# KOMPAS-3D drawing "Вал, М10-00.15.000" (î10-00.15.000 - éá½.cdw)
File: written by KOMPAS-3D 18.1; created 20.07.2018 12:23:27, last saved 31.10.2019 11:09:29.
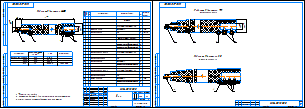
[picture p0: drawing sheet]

Sheets 1-2: A3, landscape

Document properties: Полное имя файла: D:\Magna\Магна Ins\Магна ins 10\М10-00.00.000\3Д\М10-00.15.000 - Вал.cdw; Масса: 0.519317; Форматы листов документа: 2xA3

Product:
- Part/product: Вал  | designation М10-00.15.000  | pos. 0
    Масса: 0.519317
    Раздел спецификации: Сборочные единицы
    Форматы листов документа: 2xA3
    Примечание: @100~)2xA3
    source file: М10-00.15.000 - Вал.cdw
  - Body: Тело 2
      Материал: Полипропилен  ГОСТ 26996-86 (density 900 kg/m3)
  - Body: Тело 1
      Материал: Полипропилен  ГОСТ 26996-86 (density 900 kg/m3)
  - Component [standard]: Винт A.М10-6gx40.21.12Х18Н10Т ГОСТ 11074-93  | pos. 4  | Материал: Сталь 12Х18Н10Т ГОСТ 5632-72; Масса: 0.0191; Раздел спецификации: Стандартные изделия; additional columns: А.М10-6gx40.21.12Х18Н10Т; Сталь 12Х18Н10Т ГОСТ 5632-72; source file: C:\Users\User\AppData\Local\Temp\..\..\..\..\..\Program Files\ASCON\KOMPAS-3D v18\Libs\PartLib\DATA\VAULT\methods\kompas\3d\PLib_Screw_GOST_11074-84_900.m3d
  - Component [detail]: Отбойник  | designation М1-00.25.004  | pos. 1  | Раздел спецификации: Детали; Форматы листов документа: A4; Примечание: Заим.; source file: \\192.168.87.28\Konstructor_doc\Магна\Магна Ins\Магна ins 1\Магна Ins 1-205-24В\М1-00.25.004 - Отбойник.cdw, \\192.168.87.28\Konstructor_doc\Магна\Магна Ins\Магна ins 1\Магна Ins 1-205-24В\М1-00.25.004 - Отбойник.m3d
  - Component [standard]: Винт A.М5-6gx12.21.12Х18Н10Т ГОСТ 8878-93  | qty 2  | pos. 3  | Материал: Сталь 12Х18Н10Т ГОСТ 5632-72; Масса: 0.0012; Раздел спецификации: Стандартные изделия; additional columns: А.М5-6gx12.21.12Х18Н10Т; Сталь 12Х18Н10Т ГОСТ 5632-72; source file: C:\Users\User\AppData\Local\Temp\..\..\..\..\..\Program Files\ASCON\KOMPAS-3D v18\Libs\PartLib\DATA\VAULT\methods\kompas\3d\PLib_Screw_GOST_8878-84_900.m3d
  - Component [detail]: Фиксатор  | designation М5-00.20.002  | pos. 1
      Материал: Труба 30х4-12Х18Н10Т ГОСТ 9940-81
      Масса: 0.1021
      Раздел спецификации: Детали
      Примечание: Заим.
      Плотность: 7900
      source file: ..\..\..\Магна ins 5\М5-00.00.000 - Насос Магна ins 5-C-N\3Д модель\М5-00.20.002 - Фиксатор.m3d
  - Component [detail]: Вал  | designation М10-00.15.001  | pos. 2
      Масса: 0.3957
      Раздел спецификации: Детали
      Форматы листов документа: 2xA3
      Примечание: @100~)2xA3
      Плотность: 2000
      source file: М10-00.15.001 - Вал.cdw, М10-00.15.001 - Вал.m3d
  - Component: Вал  | designation М10-00.15.001-01  | pos. 5  | Раздел спецификации: Стандартные изделия
  - Component: Винт A.М6-6gx16.21.12Х18Н10Т ГОСТ 8878-93  | pos. 7  | Раздел спецификации: Стандартные изделия
  - Component: Фиксатор  | designation М10-00.15.002  | pos. 6  | Раздел спецификации: Стандартные изделия; Форматы листов документа: А4; source file: М10-00.15.002 - Фиксатор.cdw
  - Component: Вал  | designation М10-00.15.001-02  | pos. 8  | Раздел спецификации: Стандартные изделия
  - Component: Фиксатор  | designation М11-00.01.002  | pos. 9  | Раздел спецификации: Стандартные изделия; Форматы листов документа: А4; Примечание: Заим.
  - Component: Винт A.М6-6gx16.21.12Х18Н10Т ГОСТ 8878-93  | pos. 10  | Раздел спецификации: Стандартные изделия

Title block, sheet 1: Наименование: Вал; designation: М10-00.15.000; Масса: 0,52; scale: 1:1; sheet number: 1; Количество листов документа: 2; organisation: АО «Астерион»; Форматы листов документа: A3; stored path: Z:\Магна\Магна Ins\Магна ins 10\М10-00.00.000\3Д\М10-00.15.000 - Вал.cdw; Разработал: Милов; Т. контр.: Лучихин; Утвердил: Милов
Title block, sheet 2: sheet number: 2

Views: Вид 1, Местный разрез 1, Местный разрез 2, Сверху, Проекционный вид 2, Вид 3, Вид 4
Referenced files in Z:\Магна\Магна Ins\Магна ins 10\М10-00.00.000\3Д\: М10-00.15.001 - Вал.m3d, М10-00.15.000 - Вал.a3d
Referenced files in Z:\Магна\Магна Ins\Магна ins 5\М5-00.00.000 - Насос Магна ins 5-C-N\3Д модель\: М5-00.20.002 - Фиксатор.m3d
Referenced files in D:\Magna\Магна Ins\Магна ins 10\М10-00.00.000\3Д\..\..\..\Магна ins 5\М5-00.00.000 - Насос Магна ins 5-C-N\3Д модель\: М5-00.20.002 - Фиксатор.m3d
Referenced files in D:\Magna\Магна Ins\Магна ins 10\М10-00.00.000\3Д\: М10-00.15.001 - Вал.m3d, М10-00.15.001 - Вал.cdw, М10-00.15.002 - Фиксатор.cdw, М10-00.15.000 - Вал.a3d
Referenced files in D:\Magna\Магна Ins\Магна ins 5\М5-00.00.000 - Насос Магна ins 5-C-N\3Д модель\: М5-00.20.002 - Фиксатор.m3d
Referenced files in C:\Program Files\ASCON\KOMPAS-3D v18\Libs\PartLib\DATA\VAULT\methods\kompas\3d\: PLib_Screw_GOST_8878-84_900.m3d, PLib_Screw_GOST_11074-84_900.m3d
Referenced files in C:\Program Files\ASCON\KOMPAS-3D V16\Libs\PartLib\DATA\vault\Methods\Kompas\3D\: PLib_Screw_GOST_8878-84_900.m3d
Referenced files in C:\Program Files\ASCON\KOMPAS-3D V16\Libs\PartLib\DATA\VAULT\Methods\kompas\3d\: PLib_Screw_GOST_11074-84_900.m3d
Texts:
  Габарит двигателя 63
  Длина погружной части
  L1, мм*
  L, мм
  L1 475 мм
  Габарит двигателя 71
  Габарит двигателя 80
  2D_Doc-graphic.lyt,1.000000-0-298842308658
  2D_Doc-graphic.lyt,1.000000-0-298491746024
  2D_Doc-graphic.lyt,1.000000-0-297339638027
  2D_Doc-graphic.lyt,1.000000-0-281262858143
  2D_Doc-graphic.lyt,1.000000-0-280836307480
  Фиксатор
  Заим.
  Труба 30х4-12Х18Н10Т ГОСТ 9940-81
  Винт A.М5-6gx12.21.12Х18Н10Т ГОСТ 8878-93
  Винт
  ГОСТ
  Сталь 12Х18Н10Т ГОСТ 5632-72
  @100~)2xA3
  Винт A.М10-6gx40.21.12Х18Н10Т ГОСТ 11074-93
  Винт A.М6-6gx16.21.12Х18Н10Т ГОСТ 8878-93
  3D_Doc-graphic.lyt,1.000000-4294967295-214566056024
  3D_Doc-graphic.lyt,1.000000-4294967295-280836307480
  3D_Doc-graphic.lyt,1.000000-4294967295-281262858143
  3D_Doc-graphic.lyt,1.000000-4294967295-297339638027
  3D_Doc-graphic.lyt,1.000000-4294967295-298491746024
  3D_Doc-graphic.lyt,1.000000-4294967295-298842308658
  Габарит двигателя  71
  Габарит двигателя  80
  Груп. спецификация (вариант Б) ГОСТ 2.113-75 Ф.1, 1в.
  Лифлянд
  Отбойник
Dimensions and other numbers on the sheet: 4; 2; 1; 3; 10; 14; 475; 452,5; -425; -375; 425; 375; 402,5; 352,5; 16; 30; 5; 6; 7; 19; 36; 8; 9; 21; 12Х18Н10Т; 019; 1:1; 0,52; 29.10.2019

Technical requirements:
  *Размеры для справок.
  Винт поз. 4  вклеить в вал с применением эпоксидной смолы.
  Общие допуски ГОСТ 30893.2-тК (H14, h14,  t2/2).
